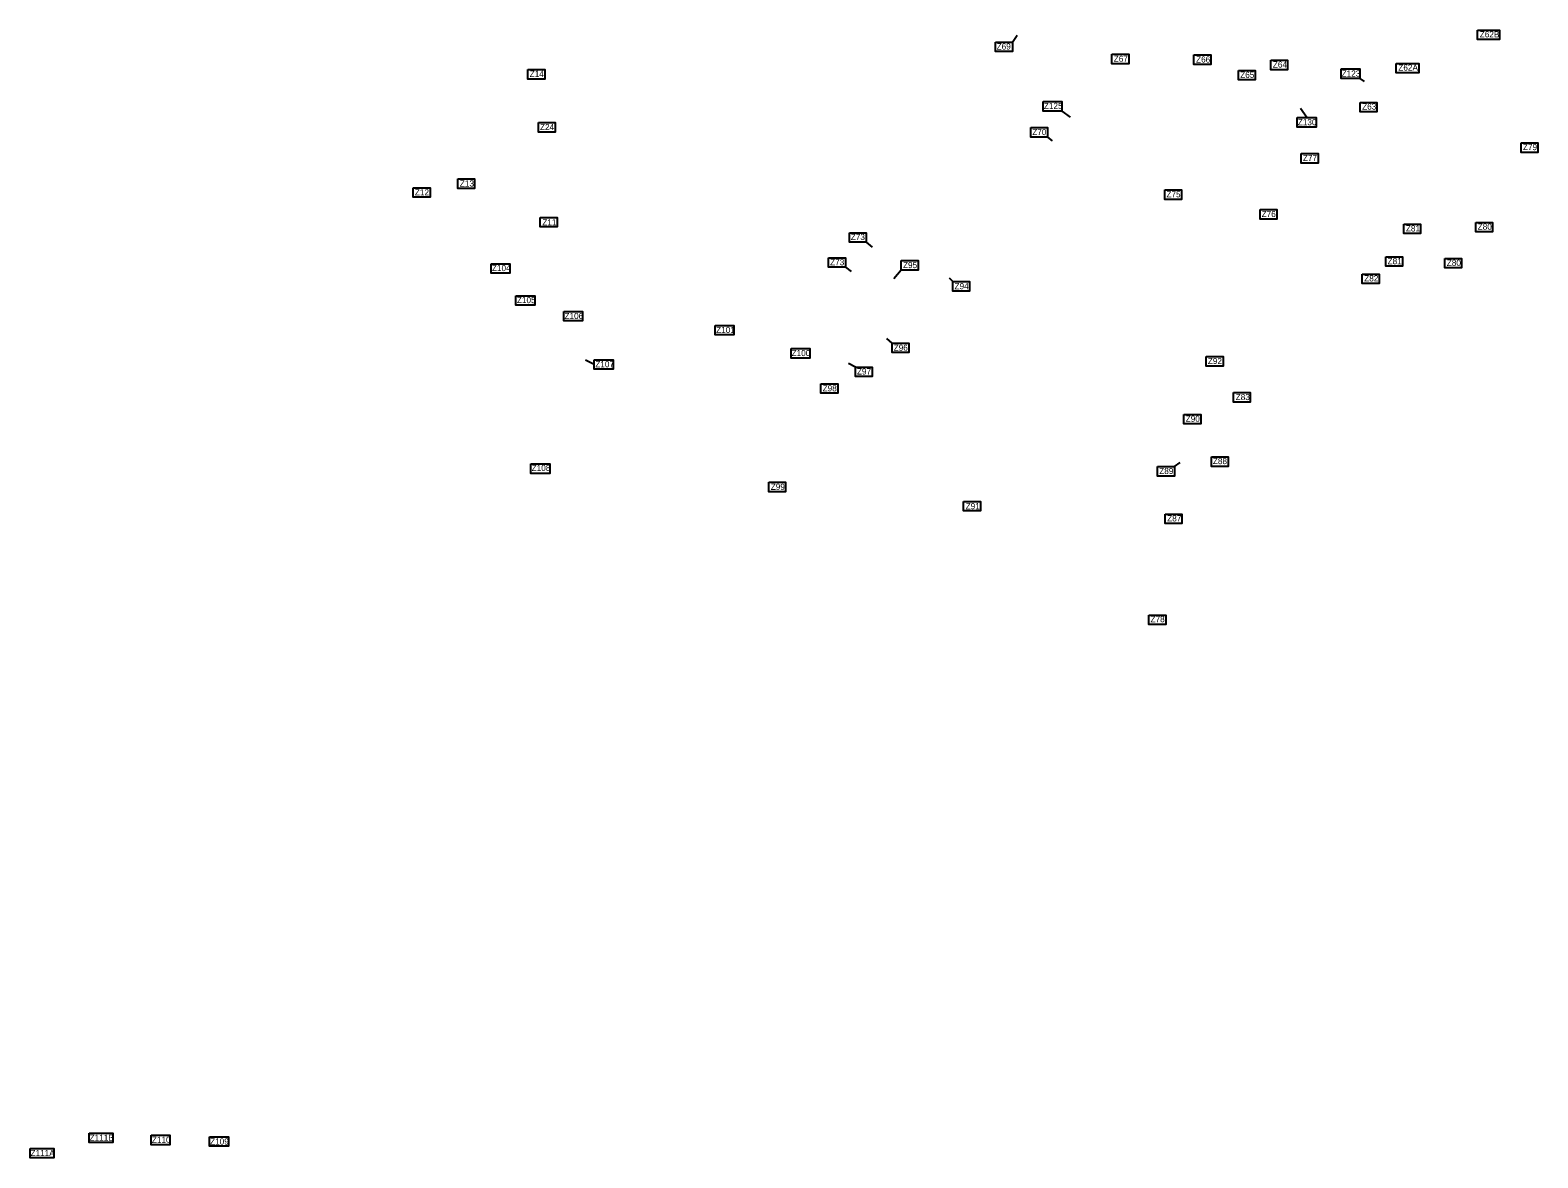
# Model space of a CAD drawing. Extents: x -443483 to -438117, y -1133472 to -1129797.
# Drawn here: x -443483 to -441026, y -1133472 to -1131633 of the extents above; entities that cross this region are included whole.
import ezdxf

# ---------------------------------------------------------------- set-up
doc = ezdxf.new("R2010")
doc.units = 0
doc.layers.add('Vrstva 3', color=7, linetype='Continuous')
doc.layers.add('Vrstva 8', color=7, linetype='Continuous')

msp = doc.modelspace()

# ---------------------------------------------------------------- linework, layer by layer
at = {"layer": 'Vrstva 3'}
for p, q in [((-441882.1, -1131652.8), (-441874.3, -1131641.5)), ((-441824.8, -1131807.6), (-441817.5, -1131813.7)), ((-442120.5, -1131979), (-442110.5, -1131987.2)), ((-442154.2, -1132019.9), (-442145, -1132026.9)), ((-442063.3, -1132024.4), (-442075.2, -1132039)), ((-441979.2, -1132043.3), (-441984.6, -1132037.9)), ((-442078.2, -1132143.6), (-442086.6, -1132135.9)), ((-442563.8, -1132178.3), (-442578.2, -1132171.1)), ((-442137.9, -1132182.9), (-442149.2, -1132176.8)), ((-441618.1, -1132344.9), (-441608.8, -1132338.2))]:
    msp.add_line(p, q, dxfattribs=at)
for points in [[(-441123.7, -1131633.4), (-441088.1, -1131633.4), (-441088.1, -1131648.8), (-441123.7, -1131648.8)], [(-441909.5, -1131652.8), (-441882.1, -1131652.8), (-441882.1, -1131668.2), (-441909.5, -1131668.2)], [(-441719.9, -1131672.7), (-441692.5, -1131672.7), (-441692.5, -1131688.1), (-441719.9, -1131688.1)], [(-441586.1, -1131673.9), (-441558.7, -1131673.9), (-441558.7, -1131689.3), (-441586.1, -1131689.3)], [(-441460.9, -1131682.5), (-441433.5, -1131682.5), (-441433.5, -1131697.9), (-441460.9, -1131697.9)], [(-441256.3, -1131687.6), (-441219.6, -1131687.6), (-441219.6, -1131703), (-441256.3, -1131703)], [(-442671.7, -1131697.8), (-442644.4, -1131697.8), (-442644.4, -1131713.2), (-442671.7, -1131713.2)], [(-441513.5, -1131699.1), (-441486.1, -1131699.1), (-441486.1, -1131714.5), (-441513.5, -1131714.5)], [(-441315.3, -1131751.1), (-441287.9, -1131751.1), (-441287.9, -1131766.5), (-441315.3, -1131766.5)], [(-442654.5, -1131784.2), (-442627.2, -1131784.2), (-442627.2, -1131799.6), (-442654.5, -1131799.6)], [(-441852.1, -1131792.2), (-441824.8, -1131792.2), (-441824.8, -1131807.6), (-441852.1, -1131807.6)], [(-441411.2, -1131834.7), (-441383.8, -1131834.7), (-441383.8, -1131850.1), (-441411.2, -1131850.1)], [(-441053, -1131817.2), (-441025.6, -1131817.2), (-441025.6, -1131832.6), (-441053, -1131832.6)], [(-442786.3, -1131876), (-442759, -1131876), (-442759, -1131891.4), (-442786.3, -1131891.4)], [(-442858.8, -1131890.4), (-442831.4, -1131890.4), (-442831.4, -1131905.8), (-442858.8, -1131905.8)], [(-441633.7, -1131893.9), (-441606.4, -1131893.9), (-441606.4, -1131909.3), (-441633.7, -1131909.3)], [(-442651.8, -1131938.6), (-442624.4, -1131938.6), (-442624.4, -1131954), (-442651.8, -1131954)], [(-441478.3, -1131925.9), (-441450.9, -1131925.9), (-441450.9, -1131941.3), (-441478.3, -1131941.3)], [(-441244, -1131949.4), (-441216.7, -1131949.4), (-441216.7, -1131964.8), (-441244, -1131964.8)], [(-441126.7, -1131946.9), (-441099.4, -1131946.9), (-441099.4, -1131962.3), (-441126.7, -1131962.3)], [(-442147.8, -1131963.6), (-442120.5, -1131963.6), (-442120.5, -1131979), (-442147.8, -1131979)], [(-442181.6, -1132004.5), (-442154.2, -1132004.5), (-442154.2, -1132019.9), (-442181.6, -1132019.9)], [(-442063.3, -1132009), (-442035.9, -1132009), (-442035.9, -1132024.4), (-442063.3, -1132024.4)], [(-441273.5, -1132002.7), (-441246.1, -1132002.7), (-441246.1, -1132018.1), (-441273.5, -1132018.1)], [(-441177.4, -1132005.6), (-441150, -1132005.6), (-441150, -1132021), (-441177.4, -1132021)], [(-442731.9, -1132014.2), (-442701.2, -1132014.2), (-442701.2, -1132029.6), (-442731.9, -1132029.6)], [(-441311.8, -1132031.1), (-441284.4, -1132031.1), (-441284.4, -1132046.5), (-441311.8, -1132046.5)], [(-441979.2, -1132043.3), (-441951.9, -1132043.3), (-441951.9, -1132058.7), (-441979.2, -1132058.7)], [(-442691.5, -1132066.2), (-442660.7, -1132066.2), (-442660.7, -1132081.6), (-442691.5, -1132081.6)], [(-442613.5, -1132092), (-442582.8, -1132092), (-442582.8, -1132107.4), (-442613.5, -1132107.4)], [(-442366.7, -1132114.8), (-442336, -1132114.8), (-442336, -1132130.2), (-442366.7, -1132130.2)], [(-442242.9, -1132152.5), (-442212.2, -1132152.5), (-442212.2, -1132167.9), (-442242.9, -1132167.9)], [(-442078.2, -1132143.6), (-442050.9, -1132143.6), (-442050.9, -1132159), (-442078.2, -1132159)], [(-442563.8, -1132170.6), (-442533.1, -1132170.6), (-442533.1, -1132186), (-442563.8, -1132186)], [(-442137.9, -1132182.9), (-442110.5, -1132182.9), (-442110.5, -1132198.2), (-442137.9, -1132198.2)], [(-441566, -1132165.5), (-441538.6, -1132165.5), (-441538.6, -1132180.9), (-441566, -1132180.9)], [(-442194.3, -1132209.9), (-442166.9, -1132209.9), (-442166.9, -1132225.3), (-442194.3, -1132225.3)], [(-441521.7, -1132224.2), (-441494.3, -1132224.2), (-441494.3, -1132239.6), (-441521.7, -1132239.6)], [(-441602.6, -1132259.7), (-441575.2, -1132259.7), (-441575.2, -1132275.1), (-441602.6, -1132275.1)], [(-441557.5, -1132329), (-441530.2, -1132329), (-441530.2, -1132344.4), (-441557.5, -1132344.4)], [(-442667.1, -1132340.5), (-442636.3, -1132340.5), (-442636.3, -1132355.9), (-442667.1, -1132355.9)], [(-441645.5, -1132344.9), (-441618.1, -1132344.9), (-441618.1, -1132360.3), (-441645.5, -1132360.3)], [(-442279.2, -1132370.4), (-442251.8, -1132370.4), (-442251.8, -1132385.8), (-442279.2, -1132385.8)], [(-441961.6, -1132401.7), (-441934.2, -1132401.7), (-441934.2, -1132417.1), (-441961.6, -1132417.1)], [(-441633.2, -1132422.4), (-441605.8, -1132422.4), (-441605.8, -1132437.8), (-441633.2, -1132437.8)], [(-441659.5, -1132587.1), (-441632.1, -1132587.1), (-441632.1, -1132602.4), (-441659.5, -1132602.4)], [(-443387, -1133431.3), (-443348.5, -1133431.3), (-443348.5, -1133446.7), (-443387, -1133446.7)], [(-443286.1, -1133434.8), (-443255.3, -1133434.8), (-443255.3, -1133450.2), (-443286.1, -1133450.2)], [(-443190.7, -1133437.1), (-443160, -1133437.1), (-443160, -1133452.5), (-443190.7, -1133452.5)], [(-443483.2, -1133456.1), (-443444.8, -1133456.1), (-443444.8, -1133471.5), (-443483.2, -1133471.5)]]:
    msp.add_lwpolyline(points, close=True, dxfattribs=at)
at = {"layer": 'Vrstva 8'}
for p, q in [((-441315.6, -1131712), (-441308.9, -1131717.3)), ((-441801.4, -1131765.3), (-441788.2, -1131775.4)), ((-441402.4, -1131775.9), (-441412.3, -1131761))]:
    msp.add_line(p, q, dxfattribs=at)
for points in [[(-441346.4, -1131696.6), (-441315.6, -1131696.6), (-441315.6, -1131712), (-441346.4, -1131712)], [(-441832.2, -1131749.9), (-441801.4, -1131749.9), (-441801.4, -1131765.3), (-441832.2, -1131765.3)], [(-441417.8, -1131775.9), (-441387.1, -1131775.9), (-441387.1, -1131791.3), (-441417.8, -1131791.3)]]:
    msp.add_lwpolyline(points, close=True, dxfattribs=at)

# ---------------------------------------------------------------- texts
at = {"layer": 'Vrstva 3'}
for s, p in [('Z62B', (-441120.3, -1131645.2)), ('Z69', (-441907.8, -1131665)), ('Z67', (-441716.9, -1131685)), ('Z66', (-441582.7, -1131686.2)), ('Z64', (-441457.5, -1131694.4)), ('Z62A', (-441253, -1131699.4)), ('Z14', (-442668.9, -1131709.6)), ('Z65', (-441510.7, -1131711.2)), ('Z63', (-441311.9, -1131762.9)), ('Z24', (-442652.1, -1131796.3)), ('Z70', (-441849.7, -1131804.5)), ('Z77', (-441408.5, -1131846.7)), ('Z79', (-441049.9, -1131829)), ('Z13', (-442782.8, -1131888.3)), ('Z12', (-442856.1, -1131902.7)), ('Z75', (-441631, -1131906)), ('Z76', (-441475.8, -1131938.1)), ('Z11', (-442648.3, -1131951.5)), ('Z81', (-441240.7, -1131961.6)), ('Z80', (-441123.6, -1131958.7)), ('Z73', (-442145.5, -1131975.5)), ('Z73', (-442179.2, -1132016.6)), ('Z95', (-442060.4, -1132021.3)), ('Z81', (-441270.5, -1132014.9)), ('Z80', (-441174, -1132017.7)), ('Z104', (-442730.5, -1132026.2)), ('Z82', (-441308.6, -1132043)), ('Z94', (-441976.4, -1132055.7)), ('Z105', (-442689.8, -1132078.4)), ('Z106', (-442612.2, -1132104.3)), ('Z101', (-442365, -1132127)), ('Z100', (-442242, -1132164.7)), ('Z96', (-442075.6, -1132156)), ('Z107', (-442562, -1132182.9)), ('Z92', (-441563.5, -1132177.7)), ('Z97', (-442135.5, -1132194.7)), ('Z98', (-442191.4, -1132222.2)), ('Z83', (-441518.1, -1132236.4)), ('Z90', (-441599.6, -1132271.8)), ('Z88', (-441555.3, -1132340.8)), ('Z108', (-442665.7, -1132352)), ('Z89', (-441642.7, -1132357)), ('Z99', (-442276, -1132382.7)), ('Z91', (-441958.3, -1132414.3)), ('Z87', (-441629.8, -1132434.2)), ('Z78', (-441656.9, -1132598.5)), ('Z111B', (-443386.3, -1133443.6)), ('Z110', (-443284.8, -1133447.1)), ('Z111A', (-443482.6, -1133468.7)), ('Z109', (-443189.9, -1133449.9))]:
    msp.add_text(s, height=10, dxfattribs=at).set_placement(p)
at = {"layer": 'Vrstva 8'}
for s, p in [('Z123', (-441345.4, -1131709.1)), ('Z125', (-441830.8, -1131761.9)), ('Z130', (-441416.9, -1131788.4))]:
    msp.add_text(s, height=10, dxfattribs=at).set_placement(p)

doc.saveas('drawing.dxf')
